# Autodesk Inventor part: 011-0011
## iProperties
Created: 2007-02
Part Number: 011-0011
Project: GDB380
Material: Al Cu Mg 4
Description: Semelle
Document SubType Name: Modeling
Designer: GG5883
Stock Number: 11-0011
Checked By: GG5883
Author: GG5883
Revision Number: 00
Title: SEMELLE
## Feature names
1. Appui plan inférieur
2. Appui glissière [Extrusion]
3. appui mors fixe [Extrusion]
4. passage axe blocage [Hole]
5. fixation mors fixe [Hole]
6. fixation2 mors fixe [Rectangular Pattern]
7. Passage goupille [Hole]
8. fixation droite semelle [Hole]
9. Rainure ablong [Extrusion]
10. Miroir1 [Mirror]
11. Corps dérivé1 [Tagging]
